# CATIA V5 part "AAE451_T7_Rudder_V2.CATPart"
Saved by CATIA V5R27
Part number: rudder
Bounding box of the stored display mesh (mm): x 167.237 to 222.987, y -5.402 to 5.346, z 23.3 to 200
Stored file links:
  W:\AAE 451\AAE451_T7_TailAssembly_V2\AAE451_T7_Rudder_V2.CATPart
  CATDrawing1.CATDrawing
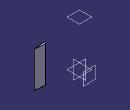
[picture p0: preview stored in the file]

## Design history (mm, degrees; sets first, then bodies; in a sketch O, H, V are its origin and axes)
Set1 "GeometryFromExcel"
  Point1: (1, 0.001, 0)
  Point2: (0.95, 0.0067, 0)
  Point3: (0.9, 0.0121, 0)
  Point4: (0.8, 0.0219, 0)
  Point5: (0.7, 0.0305, 0)
  Point6: (0.6, 0.038, 0)
  Point7: (0.5, 0.0441, 0)
  Point8: (0.4, 0.0484, 0)
  Point9: (0.3, 0.05, 0)
  Point10: (0.25, 0.0495, 0)
  Point11: (0.2, 0.0478, 0)
  Point12: (0.15, 0.0445, 0)
  Point13: (0.1, 0.039, 0)
  Point14: (0.075, 0.035, 0)
  Point15: (0.05, 0.0296, 0)
  Point16: (0.025, 0.0218, 0)
  Point17: (0.0125, 0.0158, 0)
  Point18: (0, 0, 0)
  Point19: (0.0125, -0.0158, 0)
  Point20: (0.025, -0.0218, 0)
  Point21: (0.05, -0.0296, 0)
  Point22: (0.075, -0.035, 0)
  Point23: (0.1, -0.039, 0)
  Point24: (0.15, -0.0445, 0)
  Point25: (0.2, -0.0478, 0)
  Point26: (0.25, -0.0495, 0)
  Point27: (0.3, -0.05, 0)
  Point28: (0.4, -0.0484, 0)
  Point29: (0.5, -0.0441, 0)
  Point30: (0.6, -0.038, 0)
  Point31: (0.7, -0.0305, 0)
  Point32: (0.8, -0.0219, 0)
  Point33: (0.9, -0.0121, 0)
  Point34: (0.95, -0.0067, 0)
  Point35: (1, -0.001, 0)
  Point36: (1, 0.001, 0)
  Point37: (0.95, 0.0067, 0)
  Point38: (0.9, 0.0121, 0)
  Point39: (0.8, 0.0219, 0)
  Point40: (0.7, 0.0305, 0)
  Point41: (0.6, 0.038, 0)
  Point42: (0.5, 0.0441, 0)
  Point43: (0.4, 0.0484, 0)
  Point44: (0.3, 0.05, 0)
  Point45: (0.25, 0.0495, 0)
  Point46: (0.2, 0.0478, 0)
  Point47: (0.15, 0.0445, 0)
  Point48: (0.1, 0.039, 0)
  Point49: (0.075, 0.035, 0)
  Point50: (0.05, 0.0296, 0)
  Point51: (0.025, 0.0218, 0)
  Point52: (0.0125, 0.0158, 0)
  Point53: (0, 0, 0)
  Point54: (0.0125, -0.0158, 0)
  Point55: (0.025, -0.0218, 0)
  Point56: (0.05, -0.0296, 0)
  Point57: (0.075, -0.035, 0)
  Point58: (0.1, -0.039, 0)
  Point59: (0.15, -0.0445, 0)
  Point60: (0.2, -0.0478, 0)
  Point61: (0.25, -0.0495, 0)
  Point62: (0.3, -0.05, 0)
  Point63: (0.4, -0.0484, 0)
  Point64: (0.5, -0.0441, 0)
  Point65: (0.6, -0.038, 0)
  Point66: (0.7, -0.0305, 0)
  Point67: (0.8, -0.0219, 0)
  Point68: (0.9, -0.0121, 0)
  Point69: (0.95, -0.0067, 0)
  Point70: (1, -0.001, 0)
  Curve1: Elements (Point36; Point37; Point38; Point39; Point40; Point41; Point42; Point43; Point44; Point45; Point46; Point47; Point48; Point49; Point50; Point51; Point52; Point53; Point54; Point55; Point56; Point57; Point58; Point59; Point60; Point61; Point62; Point63; Point64; Point65; Point66; Point67; Point68; Point69; Point70)
  Sketch1 on xy-plane, origin (0, 0, 0), H (1, 0, 0), V (0, 1, 0)
    projected curve E1 from edge of Curve1
    line L1 (1, 0.001) -> (1.0001, -0.001)
    point P3 (1, 0.001)
    point P4 (1.0001, -0.001)
    reference projected point E2 (1, 0.001) from Point1
    reference projected point E3 (1, -0.001) from Point35
    frozenspline C1
    line L2 (222.9868, -0.27) -> (222.9868, 0.1983)
    coincidence: P3 E2, P4 E3
    fix: C1
Body1 (main body)
  Plane1: type Offset, RefPlane xy-plane, Offset 225
  Sketch2 on xy-plane, origin (0, 0, 0), H (1, 0, 0), V (0, 1, 0)
    projected curve E1 from Sketch1.C1
    point P1 (222.9868, 0.1983)
    line L1 (222.9868, 0.1983) -> (222.9868, -0.27)
    point P3 (222.9868, 0.1983)
    coincidence: P3 P1
  Sketch3 on Plane1, origin (0, 0, 225), H (1, 0, 0), V (0, 1, 0)
    frozenspline C1
    line L1 (222.9868, 0.1983) -> (222.9868, -0.1225)
    fix: C1
  Loft1: solid, Sections (Sketch2; Sketch3)
  Plane2: type Offset, RefPlane zx-plane, Offset 50
  Sketch4 on Plane2, origin (0, 50, 0), H (0, 0, 1), V (1, 0, 0)
    line L1 (0, 227.8345) -> (23.3, 227.8345)
    line L2 (23.3, 227.8345) -> (23.3, -7.6138)
    line L3 (23.3, -7.6138) -> (0, -7.6138)
    line L4 (0, -7.6138) -> (0, 227.8345)
    reference projected line E1 (0, 222.9868) -> (0, -0.0132) from edge [face of Loft1 | face of Loft1]
    distance L4 L2 = 23.3
    distance L1 L3 = 235.4483
    vertical: L4 V, L2 V
    horizontal: L1 H, L3 H
    coincidence: L4 E1
  Pocket1: profile Sketch4, direction (0, -1, 0), up to zx-plane
  Sketch5 on zx-plane, origin (0, 0, 0), H (-1, 0, 0), V (0, 0, 1)
    line L1 (-222.9868, 200) -> (-167.2368, 200)
    line L2 (-167.2368, 200) -> (-167.2368, 23.3)
    line L3 (-167.2368, 23.3) -> (-222.9868, 23.3)
    line L4 (-222.9868, 23.3) -> (-222.9868, 0)
    point P6 (-57.3836, 225)
    line L5 (-57.3836, 225) -> (-222.9868, 225)
    line L6 (-222.9868, 225) -> (-222.9868, 200)
    reference projected line E1 (-222.9868, 23.3) -> (-222.9868, 225) from edge [face of Loft1 | face of Loft1]
    reference projected line E2 (-222.9868, 225) -> (-70.2471, 225) from edge [face of Loft1 | face of Loft1]
    reference projected line E3 (-222.9868, 0) -> (-222.9868, 23.3) from edge [end face of Pocket1 | face of Loft1]
    reference projected line E4 (-7.2628, 23.3) -> (-222.9868, 23.3) from edge [face of Loft1 | face of Pocket1 from Sketch4.L2]
    reference projected line E5 (-222.9868, 23.3) -> (-222.9868, 225) from edge [face of Loft1 | face of Loft1]
    line L7 (-222.9868, 0) -> (12.8757, 0)
    line L8 (12.8757, 0) -> (-57.3836, 225)
    point P9 (-57.3836, 225)
    reference projected line E6 (0.0129, 0) -> (-7.2628, 23.3) from edge [face of Loft1 | end face of Pocket1]
    distance L2 E5 = 55.75
    distance L5 L1 = 25
    horizontal: L1 H, L3 H
    vertical: L2 V
    coincidence: L6 E1, L5 E2, L4 E3, L3 E4, L7 H, P9 P6
    parallelism: L8 E6
  Pocket2: profile Sketch5, direction (0, -1, 0), through (limit type 3), opposite side through (limit type 3)
  Fillet1: radius 5, on edge [face of Pocket2 from Sketch5.L2 | face of Loft1]; edge [face of Loft1 | face of Pocket2 from Sketch5.L2]
  Sketch6 on face of Pocket2 from Sketch5.L2, origin (167.2368, 0, 0), H (0, -1, 0), V (0, 0, 1)
    line L1 (-0.5, 46.3) -> (0.5, 46.3)
    line L2 (0.5, 46.3) -> (0.5, 30.3)
    line L3 (0.5, 30.3) -> (-0.5, 30.3)
    line L4 (-0.5, 30.3) -> (-0.5, 46.3)
    reference projected line E1 (-5.3563, 23.3) -> (-0.3563, 23.3) from edge [face of Pocket2 | face of Fillet1]
    line L5 (-0.5, 193) -> (0.5, 193)
    line L6 (0.5, 193) -> (0.5, 177)
    line L7 (0.5, 177) -> (-0.5, 177)
    line L8 (-0.5, 177) -> (-0.5, 193)
    reference projected line E3 (-0.1225, 200) -> (-5.1226, 200) from edge [face of Pocket2 from Sketch5.L1 | face of Fillet1]
    distance L3 E1 = 7
    length L2 = 16
    length L1 = 1
    distance L5 E3 = 7
    length L6 = 16
    length L7 = 1
    horizontal: L1 H, L3 H, L5 H, L7 H
    vertical: L2 V, L4 V, L6 V, L8 V
    symmetry: L4 L2 V, L8 L6 V
  Pocket3: profile Sketch6, direction (1, 0, 0), length 13.7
